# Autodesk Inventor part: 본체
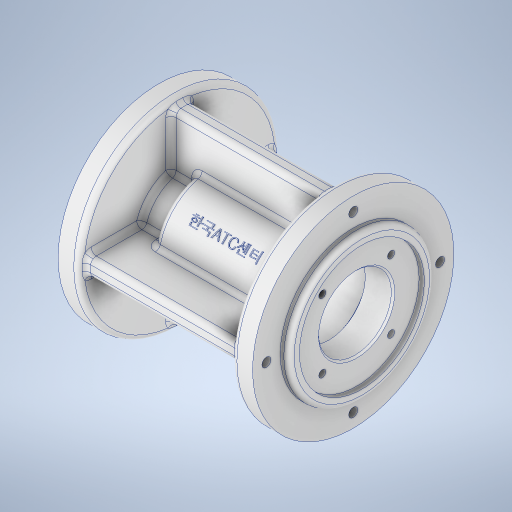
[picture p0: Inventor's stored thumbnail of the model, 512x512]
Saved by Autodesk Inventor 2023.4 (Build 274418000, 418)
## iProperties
Created: 2024-10
Part Number: 본체
Material: 알루미늄 6061
Document SubType Name: Modeling
Designer: 11
Density: 2.7 g/cm^3
Appearance: 알루미늄 - 평지
Mass: 1164.55 g
Surface Area: 972.22 cm^2
Volume: 431.315 cm^3
Author: 11
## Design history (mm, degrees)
sketch "스케치1"
  geometry: L1 (-72, 0)-(-72, 33); L2 (-75, 36)-(-76, 36); L3 (-76, 36)-(-76, 39); L4 (-73, 42)-(-71, 42); L5 (-71, 42)-(-71, 58); L6 (-71, 58)-(-62, 58); L7 (-59, 55)-(-59, 26); L8 (-56, 23)-(-47, 23); L9 (-44, 26)-(-44, 27); L10 (-41, 30)-(26, 30); L11 (29, 33)-(29, 55); L12 (32, 58)-(41, 58); L13 (41, 58)-(41, 42); L14 (41, 42)-(43, 42); L15 (46, 39)-(46, 36); L16 (46, 36)-(43, 36); L17 (43, 36)-(43, 22); L18 (42, 21)-(27, 21); L19 (27, 21)-(27, 22); L20 (24, 25)-(-24, 25); L21 (-27, 22)-(-27, 21); L22 (-27, 21)-(-38.4, 21); L23 (-39, 20.4)-(-39, 18); L24 (-39, 18)-(-57, 18); L25 (-57, 18)-(-57, 16); L26 (-57, 16)-(-60.4, 16); L27 (-61, 15.4)-(-61, 10.5); L28 (-61, 10.5)-(-61, 10.5); L29 (-64, 7.5)-(-64, 0); L30 (-64, 0)-(-72, 0); L31 (-202.175, 0)-(202.175, 0); L32 (42, 21)-(43, 22); A1 r 3 centre (-61, 7.5) between (-61, 10.5) and (-64, 7.5); A2 r 0.6 centre (-60.4, 15.4) between (-60.4, 16) and (-61, 15.4); A3 r 0.6 centre (-38.4, 20.4) between (-38.4, 21) and (-39, 20.4); A4 r 3 centre (-24, 22) between (-24, 25) and (-27, 22); A5 r 3 centre (24, 22) between (27, 22) and (24, 25); A6 r 3 centre (-75, 33) between (-72, 33) and (-75, 36); A7 r 3 centre (-56, 26) between (-59, 26) and (-56, 23); A8 r 3 centre (-47, 26) between (-47, 23) and (-44, 26); A9 r 3 centre (-41, 27) between (-41, 30) and (-44, 27); A10 r 3 centre (26, 33) between (26, 30) and (29, 33); A11 r 3 centre (-62, 55) between (-59, 55) and (-62, 58); A12 r 3 centre (32, 55) between (32, 58) and (29, 55); A13 r 3 centre (-73, 39) between (-73, 42) and (-76, 39); A14 r 3 centre (43, 39) between (46, 39) and (43, 42); 9 further points
  constraints: 64 end point, 28 point on circle, 28 tangent, 23 perpendicular, 14 centre point, 11 equal radius, 10 point on line, 3 midpoint, 2 coincident, 1 horizontal, 1 horizontal alignment, 1 vertical, 1 vertical alignment
  dimensions: "d0" = 15 distance between parallel lines of L7 L9; "d1" = 4 distance between parallel lines of L1 L3; "d3" = 21 diameter of L28 L31; "d4" = 32 diameter of L26 L31; "d5" = 36 diameter of L24 L31; "d6" = 42 diameter of L22 L31; "d7" = 50 diameter of L20 L31; "d8" = 72 diameter of L16 L31; "d9" = 84 diameter of L14 L31; "d10" = 84 diameter of L4 L31; "d11" = 116 diameter of L6 L31; "d12" = 60 diameter of L10 L31; "d14" = 12 distance between parallel lines of L13 L11; "d15" = 5 distance between parallel lines of L13 L15; "d16" = 12 distance between parallel lines of L5 L7; "d17" = 5 distance between parallel lines of L3 L5; "d19" = 54 distance between parallel lines of L19 L21; "d20" = 3 distance between parallel lines of L17 L15; "d21" = 16 distance between parallel lines of L19 L17; "d22" = 3 distance between parallel lines of L29 L27; "d23" = 4 distance between parallel lines of L27 L25; "d24" = 18 distance between parallel lines of L25 L23; "d26" = 72 diameter of L2 L31; "d27" = 46 diameter of L8 L31; "d28" = 82 distance between parallel lines of L17 L23; "d29" = 122 distance between parallel lines of L15 L3; "d30" = 3 radius of A1; "d31" = 0.6 radius of A2; "d32" = 1 distance of L18.start point (43, 21); "d33" = 45 deg angle of L18 L32; "d34" = 3 radius of A6 (derived)
revolve "회전1" sketch "스케치1" stored, may be unused: angle "d35" = 90 deg
sketch "스케치2"
  geometry: L1 (-59, -55)-(-59, 55) reference; L2 (29, -55)-(29, 55) reference; L3 (29, 54)-(-59, 54); 1 further point
  constraints: 2 end point, 2 point on line, 1 perpendicular
  dimensions: "d36" = 54 distance from line of L3 point (0, 0)
feature "리브1" sketch "스케치2" dims "d37" = 1, "d38" = 10, "d39" = 0, "d40" = 0, "d41" = 1, "d42" = 1
fillet "모깎기1" dims "d43" = 3
fillet "모깎기2" dims "d44" = 3
sketch "스케치3" dims "d48" = 100
  geometry: C1 r 58 at (0, 0) reference; C2 r 42 at (0, 0) reference; C3 r 18 at (0, 0) reference; 3 further points
  constraints: 2 vertical alignment, 1 coincident, 2 other
hole "구멍1" sketch "스케치3" at (0, 50) diameter "d49" = 5.24223; stored, may be unused: countersink angle "d53" = 90 deg, drill point angle "d55" = 118 deg; dims "d50" = 12, "d51" = 4, "d52" = 2, "d54" = 14
sketch "스케치4" dims "d9" = 84, "d10" = 84, "d59" = 100
  geometry: C1 r 58 at (0, 0) reference; C2 r 42 at (0, 0) reference; C3 r 7.5 at (0, 0) reference; 3 further points
  constraints: 2 vertical alignment, 1 coincident, 2 other
hole "구멍2" sketch "스케치4" at (0, 50) diameter "d60" = 5.24223; stored, may be unused: countersink angle "d64" = 90 deg, drill point angle "d66" = 118 deg; dims "d9" = 84, "d10" = 84, "d61" = 12, "d62" = 4, "d63" = 2, "d65" = 14
sketch "스케치5" dims "d70" = 56
  geometry: L1 (-61.999, -61.999)-(61.999, 61.999); L2 (-87.614, 0)-(87.614, 0); C1 r 2.621 at (50, 0) reference; C2 r 2.621 at (0, -50) reference; C3 r 2.621 at (-50, 0) reference; C4 r 2.621 at (0, 50) reference; C5 r 58 at (0, 0) reference; C6 r 42 at (0, 0) reference; C7 r 36 at (0, 0) reference; C8 r 2.621 at (0, 50) reference; 5 further points
  constraints: 4 coincident, 4 end point, 2 midpoint, 1 horizontal, 1 point on line, 3 other
  dimensions: "d71" = 45 deg angle of L2 L1
hole "구멍3" sketch "스케치5" at (19.799, 19.799) diameter "d72" = 4.134; stored, may be unused: countersink angle "d76" = 90 deg, drill point angle "d78" = 118 deg; dims "d73" = 10, "d74" = 4, "d75" = 2, "d77" = 12
node "작업 평면2"
node "작업 평면4"
node "작업 평면5"
sketch "스케치7"
  geometry: C1 r 7.5 at (26, 0); 1 further point
  constraints: 1 centre point, 1 coincident
  dimensions: "d87" = 15 diameter of C1
extrude "돌출2" join sketch "스케치7" stored distance "d88" = 4; taper "d89" = 0 deg
fillet "모깎기3" dims "d90" = 3
node "작업 평면6"
sketch "스케치8"
  geometry: C1 r 7.5 at (0, 0) reference; 2 further points
  constraints: 1 coincident
hole "구멍4" sketch "스케치8" at (0, 0) diameter "d92" = 5.1881; stored, may be unused: countersink angle "d96" = 90 deg, drill point angle "d98" = 118 deg; dims "d93" = 15, "d94" = 4, "d95" = 2, "d97" = 18
node "작업 평면10" dims "d9" = 84
  node "작업 평면9" dims "d9" = 84
sketch "스케치9" dims "d9" = 84
  geometry: L1 (-48.5, 58)-(-48.5, -58) reference; 2 further points
  constraints: 1 horizontal alignment, 1 other
  dimensions: "d100" = 52 distance from line of point (3.5, 0) L1
feature "엠보싱1" sketch "스케치9" dims "d9" = 84, "d101" = 0.5, "d102" = 0
node "솔리드1"
pattern_circular "원형 패턴1" dims angle "d46" = 360 deg
pattern_circular "원형 패턴2" dims angle "d57" = 360 deg
pattern_circular "원형 패턴3" dims angle "d68" = 360 deg
pattern_circular "원형 패턴4" dims angle "d80" = 360 deg
mirror "미러2"
mirror "미러3"
node "투영된 루프1"
node "투영된 루프2"
node "투영된 루프3"
node "투영된 루프4"
feature "A9D066F2-1C7D-4E18-AEED-F7BC21143FA4" dims "d92" = 5.1881, "d93" = 15, "d94" = 4, "d95" = 2, "d96" = 90 deg, "d97" = 18, "d98" = 118 deg
other parameters: "d86" = 4, "d99" = 90 deg
